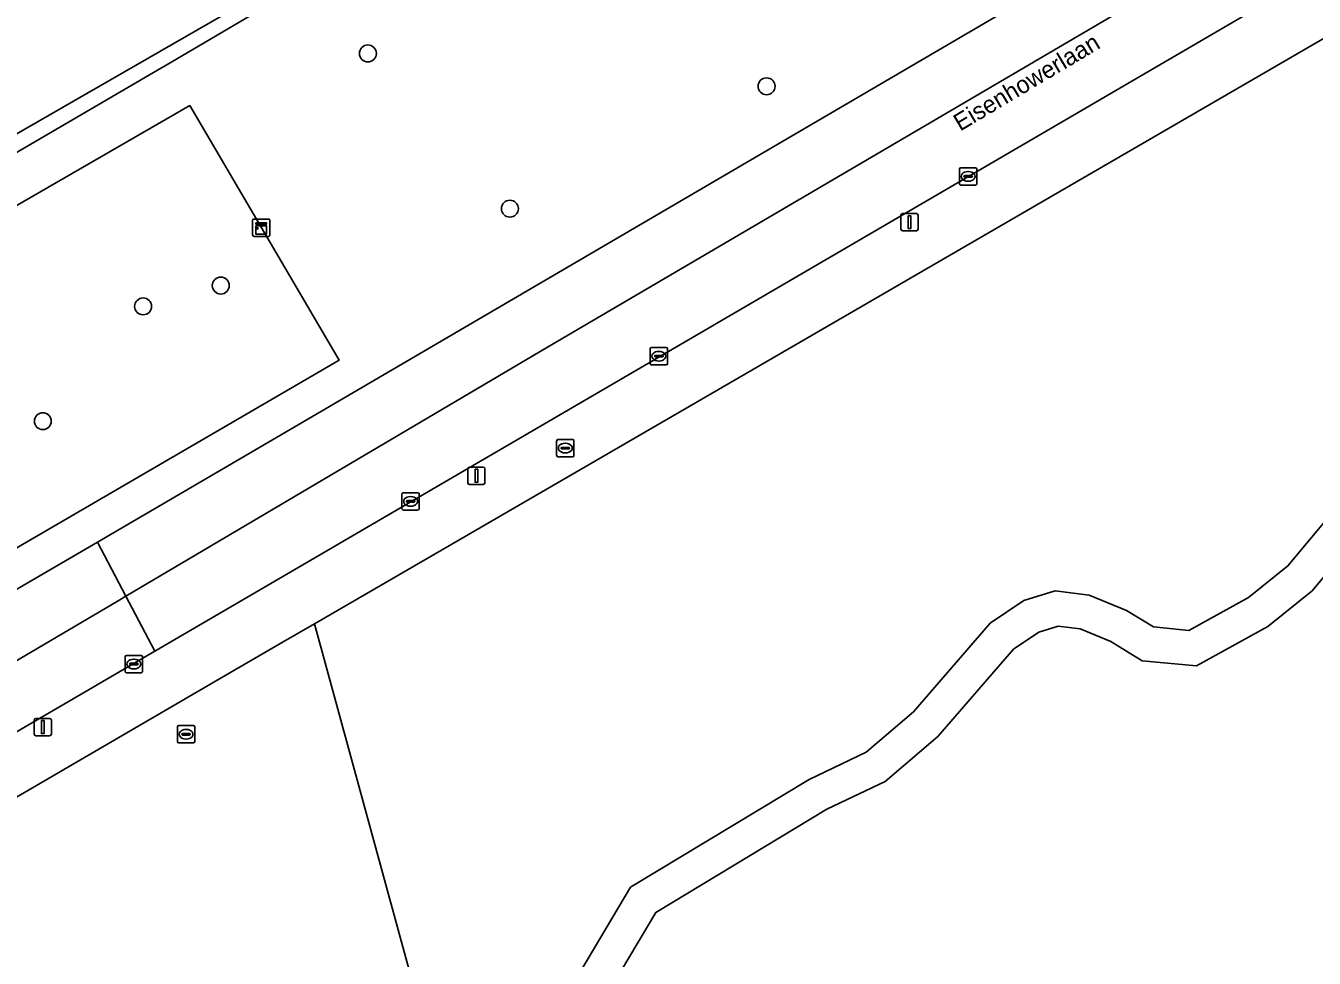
# Model space of a CAD drawing. Extents: x 162879 to 165540, y 384011 to 385181.
# Drawn here: x 163130.7 to 163205.2, y 384332.4 to 384386.3 of the extents above; entities that cross this region are included whole.
import ezdxf

# ---------------------------------------------------------------- set-up
doc = ezdxf.new("R2010")
doc.units = 0
for name, color, linetype in [('IMGEO_Berm_groen', 7, 'Continuous'), ('IMGEO_Boom', 7, 'Continuous'), ('IMGEO_Groenvoorziening', 7, 'Continuous'), ('IMGEO_Kast', 7, 'Continuous'), ('IMGEO_Kolk', 7, 'Continuous'), ('IMGEO_Lichtmast', 7, 'Continuous'), ('IMGEO_Loofbos', 7, 'Continuous'), ('IMGEO_Openbare_ruimte_label', 7, 'Continuous'), ('IMGEO_Rijbaan_regionaal_gesloten', 7, 'Continuous'), ('IMGEO_Rioolput', 7, 'Continuous'), ('IMGEO_Voetpad_onverhard', 7, 'Continuous')]:
    doc.layers.add(name, color=color, linetype=linetype)

msp = doc.modelspace()

# ---------------------------------------------------------------- linework, layer by layer
at = {"layer": 'IMGEO_Berm_groen'}
for points in [[(162958.296, 384257.287), (162992.107, 384275.576), (162992.774, 384275.937), (163000, 384279.879), (163047.71, 384305.906), (163065.69, 384316.128), (163134.875, 384356.468), (163142.16, 384360.715), (163149.867, 384365.229), (163197.962, 384393.395), (163222.445, 384407.821), (163353.264, 384484.905)], [(163290.991, 384473.343), (163273.206, 384463), (163256.317, 384453.078), (163211.461, 384426.757), (163138.843, 384384.023), (163138.358, 384383.738), (163124.723, 384375.774), (163103.614, 384363.445), (163068.795, 384343.295), (163033.81, 384323.482)]]:
    msp.add_lwpolyline(points, dxfattribs=at)
msp.add_lwpolyline([(163148.842, 384366.976), (163055.696, 384312.747), (162991.211, 384277.349), (162986.763, 384286.167), (162986.414, 384294.29), (162999.918, 384301.631), (163052.601, 384331.084), (163140.211, 384381.691)], close=True, dxfattribs=at)
at = {"layer": 'IMGEO_Boom'}
for centre in [(163150.504, 384384.702), (163173.541, 384382.804), (163158.709, 384375.733), (163142.004, 384371.289), (163137.518, 384370.087), (163131.724, 384363.452)]:
    msp.add_circle(centre, 0.489, dxfattribs=at)
at = {"layer": 'IMGEO_Groenvoorziening'}
for points in [[(163596.733, 384620.336), (163590.474, 384616.677), (163584.15, 384613.033), (163543.932, 384589.276), (163500, 384563.326), (163392.794, 384500), (163356.886, 384478.81), (163202.966, 384387.982), (163138.189, 384350.166), (163091.98, 384323.19), (163060.001, 384304.827), (163000, 384271.727), (162995.148, 384269.194), (162989.657, 384266.154), (162987.354, 384264.896)], [(162987.751, 384263.155), (162988.941, 384263.017), (163012.114, 384262.491), (163015.053, 384262.437), (163010.306, 384266.101), (163010.259, 384272.54), (163015.983, 384275.987), (163044.781, 384289.14), (163054.546, 384290.508), (163057.113, 384293.326), (163061.012, 384294.747), (163074.049, 384307.518), (163078.609, 384311.03), (163103.227, 384326.016), (163139.713, 384347.269), (163141.708, 384348.431), (163145.603, 384350.692), (163147.412, 384351.742), (163229.097, 384399.154), (163272.33, 384424.447), (163305.16, 384443.366)]]:
    msp.add_lwpolyline(points, dxfattribs=at)
at = {"layer": 'IMGEO_Kast'}
for p, q in [((163143.844, 384374.205), (163143.844, 384375.046)), ((163143.844, 384375.046), (163143.844, 384374.205)), ((163143.919, 384375.13), (163144.76, 384375.13)), ((163144.76, 384375.13), (163143.919, 384375.13)), ((163144.844, 384375.055), (163144.844, 384374.214)), ((163144.844, 384374.214), (163144.844, 384375.055)), ((163144.769, 384374.13), (163143.928, 384374.13)), ((163143.928, 384374.13), (163144.769, 384374.13))]:
    msp.add_line(p, q, dxfattribs=at)
for points in [[(163144.039, 384374.92), (163144.639, 384374.92), (163144.639, 384374.835), (163144.039, 384374.835), (163144.039, 384374.92)], [(163144.039, 384374.745), (163144.639, 384374.745), (163144.639, 384374.256), (163144.039, 384374.256), (163144.039, 384374.745)]]:
    msp.add_lwpolyline(points, dxfattribs=at)
msp.add_circle((163144.123, 384374.594), 0.0377, dxfattribs=at)
for centre, start, end in [((163143.922, 384375.052), 92.4484, 184.28452), ((163143.922, 384375.052), 92.4484, 184.28452), ((163144.766, 384375.052), 2.4484, 94.28452), ((163144.766, 384375.052), 2.4484, 94.28452), ((163143.922, 384374.208), 182.4484, 274.28452), ((163143.922, 384374.208), 182.4484, 274.28452), ((163144.766, 384374.208), 272.4484, 4.28452), ((163144.766, 384374.208), 272.4484, 4.28452)]:
    msp.add_arc(centre, 0.0779, start, end, dxfattribs=at)
at = {"layer": 'IMGEO_Kolk'}
for p, q in [((163184.684, 384377.173), (163184.684, 384378.025)), ((163184.759, 384378.099), (163185.611, 384378.099)), ((163185.172, 384377.879), (163185.197, 384377.879)), ((163185.685, 384378.025), (163185.685, 384377.173)), ((163184.943, 384377.593), (163184.943, 384377.605)), ((163185.381, 384377.556), (163184.983, 384377.556)), ((163184.986, 384377.642), (163185.384, 384377.642)), ((163185.195, 384377.319), (163185.17, 384377.319)), ((163185.427, 384377.605), (163185.427, 384377.593)), ((163185.611, 384377.099), (163184.759, 384377.099)), ((163166.817, 384366.782), (163166.817, 384367.634)), ((163166.892, 384367.708), (163167.744, 384367.708)), ((163167.305, 384367.488), (163167.33, 384367.488)), ((163167.818, 384367.634), (163167.818, 384366.782)), ((163167.744, 384366.708), (163166.892, 384366.708)), ((163167.076, 384367.202), (163167.076, 384367.214)), ((163167.514, 384367.165), (163167.116, 384367.165)), ((163167.119, 384367.251), (163167.517, 384367.251)), ((163167.328, 384366.928), (163167.303, 384366.928)), ((163167.56, 384367.214), (163167.56, 384367.202)), ((163152.548, 384359.319), (163153.4, 384359.319)), ((163152.473, 384358.393), (163152.473, 384359.245)), ((163152.732, 384358.813), (163152.732, 384358.825)), ((163153.17, 384358.776), (163152.772, 384358.776)), ((163152.775, 384358.862), (163153.173, 384358.862)), ((163152.984, 384358.539), (163152.959, 384358.539)), ((163152.961, 384359.099), (163152.986, 384359.099)), ((163153.216, 384358.825), (163153.216, 384358.813)), ((163153.474, 384359.245), (163153.474, 384358.393)), ((163153.4, 384358.319), (163152.548, 384358.319)), ((163136.485, 384348.992), (163136.485, 384349.844)), ((163136.56, 384349.918), (163137.412, 384349.918)), ((163136.973, 384349.698), (163136.998, 384349.698)), ((163137.486, 384349.844), (163137.486, 384348.992)), ((163137.412, 384348.918), (163136.56, 384348.918)), ((163136.744, 384349.412), (163136.744, 384349.424)), ((163137.182, 384349.375), (163136.784, 384349.375)), ((163136.787, 384349.461), (163137.185, 384349.461)), ((163136.996, 384349.138), (163136.971, 384349.138)), ((163137.228, 384349.424), (163137.228, 384349.412))]:
    msp.add_line(p, q, dxfattribs=at)
for points in [[(163184.684, 384377.173), (163184.684, 384378.025)], [(163184.759, 384378.099), (163185.611, 384378.099)], [(163185.685, 384378.025), (163185.685, 384377.173)], [(163185.611, 384377.099), (163184.759, 384377.099)], [(163166.817, 384366.782), (163166.817, 384367.634)], [(163166.892, 384367.708), (163167.744, 384367.708)], [(163167.818, 384367.634), (163167.818, 384366.782)], [(163167.744, 384366.708), (163166.892, 384366.708)], [(163152.548, 384359.319), (163153.4, 384359.319)], [(163152.473, 384358.393), (163152.473, 384359.245)], [(163153.474, 384359.245), (163153.474, 384358.393)], [(163153.4, 384358.319), (163152.548, 384358.319)], [(163136.485, 384348.992), (163136.485, 384349.844)], [(163136.56, 384349.918), (163137.412, 384349.918)], [(163137.486, 384349.844), (163137.486, 384348.992)], [(163137.412, 384348.918), (163136.56, 384348.918)]]:
    msp.add_lwpolyline(points, dxfattribs=at)
for centre, radius, start, end in [((163184.761, 384378.023), 0.0765, 91.55205, 178.44795), ((163184.761, 384378.023), 0.0765, 91.55205, 178.44795), ((163185.609, 384378.023), 0.0765, 1.55205, 88.44795), ((163185.609, 384378.023), 0.0765, 1.55205, 88.44795), ((163184.761, 384377.175), 0.0765, 181.55205, 268.44795), ((163184.761, 384377.175), 0.0765, 181.55205, 268.44795), ((163184.983, 384377.602), 0.0403, 85.87752, 175.75265), ((163184.98, 384377.592), 0.0366, 178.93798, 274.71019), ((163185.384, 384377.599), 0.043, 264.86636, 352.45326), ((163185.388, 384377.604), 0.0386, 1.73085, 96.63898), ((163185.609, 384377.175), 0.0765, 271.55205, 358.44795), ((163185.609, 384377.175), 0.0765, 271.55205, 358.44795), ((163166.894, 384367.632), 0.0765, 91.55205, 178.44795), ((163166.894, 384367.632), 0.0765, 91.55205, 178.44795), ((163167.742, 384367.632), 0.0765, 1.55205, 88.44795), ((163167.742, 384367.632), 0.0765, 1.55205, 88.44795), ((163166.894, 384366.784), 0.0765, 181.55205, 268.44795), ((163166.894, 384366.784), 0.0765, 181.55205, 268.44795), ((163167.116, 384367.211), 0.0403, 85.87752, 175.75265), ((163167.113, 384367.201), 0.0366, 178.93798, 274.71019), ((163167.517, 384367.208), 0.043, 264.86636, 352.45326), ((163167.521, 384367.213), 0.0386, 1.73085, 96.63898), ((163167.742, 384366.784), 0.0765, 271.55205, 358.44795), ((163167.742, 384366.784), 0.0765, 271.55205, 358.44795), ((163152.55, 384359.243), 0.0765, 91.55205, 178.44795), ((163152.55, 384359.243), 0.0765, 91.55205, 178.44795), ((163153.398, 384359.243), 0.0765, 1.55205, 88.44795), ((163153.398, 384359.243), 0.0765, 1.55205, 88.44795), ((163152.772, 384358.822), 0.0403, 85.87752, 175.75265), ((163152.769, 384358.812), 0.0366, 178.93798, 274.71019), ((163153.173, 384358.819), 0.043, 264.86636, 352.45326), ((163153.177, 384358.824), 0.0386, 1.73085, 96.63898), ((163152.55, 384358.395), 0.0765, 181.55205, 268.44795), ((163152.55, 384358.395), 0.0765, 181.55205, 268.44795), ((163153.398, 384358.395), 0.0765, 271.55205, 358.44795), ((163153.398, 384358.395), 0.0765, 271.55205, 358.44795), ((163136.562, 384349.842), 0.0765, 91.55205, 178.44795), ((163136.562, 384349.842), 0.0765, 91.55205, 178.44795), ((163137.41, 384349.842), 0.0765, 1.55205, 88.44795), ((163137.41, 384349.842), 0.0765, 1.55205, 88.44795), ((163136.562, 384348.994), 0.0765, 181.55205, 268.44795), ((163136.562, 384348.994), 0.0765, 181.55205, 268.44795), ((163136.784, 384349.421), 0.0403, 85.87752, 175.75265), ((163136.781, 384349.411), 0.0366, 178.93798, 274.71019), ((163137.185, 384349.418), 0.043, 264.86636, 352.45326), ((163137.189, 384349.423), 0.0386, 1.73085, 96.63898), ((163137.41, 384348.994), 0.0765, 271.55205, 358.44795), ((163137.41, 384348.994), 0.0765, 271.55205, 358.44795)]:
    msp.add_arc(centre, radius, start, end, dxfattribs=at)
for centre, major_axis, ratio, start_param, end_param in [((163185.171, 384377.599), (-0.387, 0.002), 0.722429, 4.712389, 7.853982), ((163185.196, 384377.599), (-0.39, 0.002), 0.717154, 1.570796, 4.712389), ((163167.304, 384367.208), (-0.387, 0.002), 0.722429, 4.712389, 7.853982), ((163167.329, 384367.208), (-0.39, 0.002), 0.717154, 1.570796, 4.712389), ((163152.96, 384358.819), (-0.387, 0.002), 0.722429, 4.712389, 7.853982), ((163152.985, 384358.819), (-0.39, 0.002), 0.717154, 1.570796, 4.712389), ((163136.972, 384349.418), (-0.387, 0.002), 0.722429, 4.712389, 7.853982), ((163136.997, 384349.418), (-0.39, 0.002), 0.717154, 1.570796, 4.712389)]:
    msp.add_ellipse(centre, major_axis=major_axis, ratio=ratio, start_param=start_param, end_param=end_param, dxfattribs=at)
at = {"layer": 'IMGEO_Lichtmast'}
for p, q in [((163181.302, 384374.553), (163181.302, 384375.353)), ((163181.302, 384375.353), (163181.302, 384374.553)), ((163181.402, 384375.453), (163182.192, 384375.453)), ((163182.192, 384375.453), (163181.402, 384375.453)), ((163182.292, 384375.353), (163182.292, 384374.553)), ((163182.292, 384374.553), (163182.292, 384375.353)), ((163182.192, 384374.453), (163181.402, 384374.453)), ((163181.402, 384374.453), (163182.192, 384374.453)), ((163156.378, 384360.799), (163157.168, 384360.799)), ((163157.168, 384360.799), (163156.378, 384360.799)), ((163156.278, 384359.899), (163156.278, 384360.699)), ((163156.278, 384360.699), (163156.278, 384359.899)), ((163157.268, 384360.699), (163157.268, 384359.899)), ((163157.268, 384359.899), (163157.268, 384360.699)), ((163157.168, 384359.799), (163156.378, 384359.799)), ((163156.378, 384359.799), (163157.168, 384359.799)), ((163131.227, 384345.372), (163131.227, 384346.172)), ((163131.227, 384346.172), (163131.227, 384345.372)), ((163131.327, 384346.272), (163132.117, 384346.272)), ((163132.117, 384346.272), (163131.327, 384346.272)), ((163132.217, 384346.172), (163132.217, 384345.372)), ((163132.217, 384345.372), (163132.217, 384346.172)), ((163132.117, 384345.272), (163131.327, 384345.272)), ((163131.327, 384345.272), (163132.117, 384345.272))]:
    msp.add_line(p, q, dxfattribs=at)
for points in [[(163181.722, 384375.328), (163181.872, 384375.328), (163181.872, 384374.578), (163181.722, 384374.578), (163181.722, 384375.328)], [(163156.698, 384360.674), (163156.848, 384360.674), (163156.848, 384359.924), (163156.698, 384359.924), (163156.698, 384360.674)], [(163131.647, 384346.147), (163131.797, 384346.147), (163131.797, 384345.397), (163131.647, 384345.397), (163131.647, 384346.147)]]:
    msp.add_lwpolyline(points, dxfattribs=at)
for centre, start, end in [((163181.402, 384375.353), 90, 180), ((163181.402, 384375.353), 90, 180), ((163182.192, 384375.353), 0, 90), ((163182.192, 384375.353), 360, 90), ((163181.402, 384374.553), 180, 270), ((163181.402, 384374.553), 180, 270), ((163182.192, 384374.553), 270, 0), ((163182.192, 384374.553), 270, 0), ((163156.378, 384360.699), 90, 180), ((163156.378, 384360.699), 90, 180), ((163157.168, 384360.699), 0, 90), ((163157.168, 384360.699), 360, 90), ((163156.378, 384359.899), 180, 270), ((163156.378, 384359.899), 180, 270), ((163157.168, 384359.899), 270, 0), ((163157.168, 384359.899), 270, 0), ((163131.327, 384346.172), 90, 180), ((163131.327, 384346.172), 90, 180), ((163132.117, 384346.172), 0, 90), ((163132.117, 384346.172), 360, 90), ((163131.327, 384345.372), 180, 270), ((163131.327, 384345.372), 180, 270), ((163132.117, 384345.372), 270, 0), ((163132.117, 384345.372), 270, 0)]:
    msp.add_arc(centre, 0.1, start, end, dxfattribs=at)
at = {"layer": 'IMGEO_Loofbos'}
for points in [[(163229.097, 384399.154), (163147.412, 384351.742), (163158.27, 384312.081), (163162.156, 384313.029), (163160.013, 384319.249), (163159.169, 384324.318), (163160.73, 384328.191), (163165.672, 384336.523), (163175.991, 384342.737), (163179.291, 384344.325), (163182.035, 384346.651), (163186.463, 384351.781), (163188.392, 384353.092), (163190.215, 384353.652), (163192.179, 384353.396), (163194.341, 384352.514), (163195.894, 384351.559), (163197.94, 384351.366), (163201.376, 384353.257), (163203.656, 384355.092), (163207.856, 384360.119)], [(163209.662, 384359.161), (163205.064, 384353.658), (163202.49, 384351.586), (163198.379, 384349.316), (163195.243, 384349.611), (163193.434, 384350.724), (163191.664, 384351.446), (163190.387, 384351.613), (163189.268, 384351.268), (163187.81, 384350.278), (163183.442, 384345.222), (163180.387, 384342.633), (163177.023, 384341.024), (163167.135, 384335.069), (163162.528, 384327.302), (163161.234, 384324.092), (163161.959, 384319.742), (163164.107, 384313.505), (163168.868, 384314.666), (163182.164, 384318.052), (163184.827, 384316.897)], [(163130.038, 384303.169), (163140.765, 384307.422), (163143.627, 384308.496), (163152.808, 384310.825), (163155.41, 384311.383), (163158.27, 384312.081), (163147.412, 384351.742), (163145.603, 384350.692), (163141.708, 384348.431), (163139.713, 384347.269), (163103.227, 384326.016)]]:
    msp.add_lwpolyline(points, dxfattribs=at)
msp.add_lwpolyline([(163140.211, 384381.691), (163052.601, 384331.084), (162999.918, 384301.631), (162986.414, 384294.29), (162986.763, 384286.167), (162991.211, 384277.349), (163055.696, 384312.747), (163148.842, 384366.976)], close=True, dxfattribs=at)
at = {"layer": 'IMGEO_Rijbaan_regionaal_gesloten'}
for points in [[(163488.662, 384588.942), (163262.486, 384457.037), (163154.214, 384393.894), (163124.264, 384376.647), (163124.723, 384375.774), (163138.358, 384383.738), (163138.843, 384384.023), (163211.461, 384426.757), (163256.317, 384453.078), (163273.206, 384463), (163290.991, 384473.343)], [(163075.431, 384317.808), (163102.908, 384333.537), (163136.085, 384353.074), (163136.524, 384353.333), (163134.875, 384356.468), (163065.69, 384316.128), (163047.71, 384305.906), (163000, 384279.879), (162992.774, 384275.937), (162992.107, 384275.576), (162958.296, 384257.287)], [(163060.001, 384304.827), (163091.98, 384323.19), (163138.189, 384350.166), (163136.524, 384353.333), (163136.085, 384353.074), (163102.908, 384333.537), (163075.431, 384317.808), (163019.119, 384286.121), (162984.518, 384267.432), (162966.682, 384257.842), (162956.166, 384251.683), (162950.166, 384247.581), (162946.914, 384245.082), (162943.802, 384242.49), (162940.823, 384239.608), (162938.038, 384236.628), (162940.725, 384234.294)]]:
    msp.add_lwpolyline(points, dxfattribs=at)
for points in [[(163354.963, 384482.045), (163353.264, 384484.905), (163222.445, 384407.821), (163197.962, 384393.395), (163149.867, 384365.229), (163142.16, 384360.715), (163134.875, 384356.468), (163136.524, 384353.333), (163160.883, 384367.724), (163225.608, 384405.722), (163256.03, 384423.663), (163336.414, 384471.12), (163346.799, 384477.262)], [(163356.886, 384478.81), (163354.963, 384482.045), (163346.799, 384477.262), (163336.414, 384471.12), (163256.03, 384423.663), (163225.608, 384405.722), (163160.883, 384367.724), (163136.524, 384353.333), (163138.189, 384350.166), (163202.966, 384387.982)]]:
    msp.add_lwpolyline(points, close=True, dxfattribs=at)
at = {"layer": 'IMGEO_Rioolput'}
for p, q in [((163161.411, 384361.47), (163161.411, 384362.322)), ((163161.486, 384362.396), (163162.338, 384362.396)), ((163162.412, 384362.322), (163162.412, 384361.47)), ((163161.67, 384361.89), (163161.67, 384361.902)), ((163162.108, 384361.853), (163161.71, 384361.853)), ((163161.713, 384361.939), (163162.111, 384361.939)), ((163161.922, 384361.616), (163161.897, 384361.616)), ((163161.899, 384362.176), (163161.924, 384362.176)), ((163162.154, 384361.902), (163162.154, 384361.89)), ((163162.338, 384361.396), (163161.486, 384361.396)), ((163139.574, 384345.86), (163140.426, 384345.86)), ((163139.499, 384344.934), (163139.499, 384345.786)), ((163139.758, 384345.354), (163139.758, 384345.366)), ((163140.196, 384345.317), (163139.798, 384345.317)), ((163139.801, 384345.403), (163140.199, 384345.403)), ((163139.987, 384345.64), (163140.012, 384345.64)), ((163140.242, 384345.366), (163140.242, 384345.354)), ((163140.5, 384345.786), (163140.5, 384344.934)), ((163140.426, 384344.86), (163139.574, 384344.86)), ((163140.01, 384345.08), (163139.985, 384345.08))]:
    msp.add_line(p, q, dxfattribs=at)
for points in [[(163161.411, 384361.47), (163161.411, 384362.322)], [(163161.486, 384362.396), (163162.338, 384362.396)], [(163162.412, 384362.322), (163162.412, 384361.47)], [(163162.338, 384361.396), (163161.486, 384361.396)], [(163139.574, 384345.86), (163140.426, 384345.86)], [(163139.499, 384344.934), (163139.499, 384345.786)], [(163140.5, 384345.786), (163140.5, 384344.934)], [(163140.426, 384344.86), (163139.574, 384344.86)]]:
    msp.add_lwpolyline(points, dxfattribs=at)
for centre, radius, start, end in [((163161.488, 384362.32), 0.0765, 91.55205, 178.44795), ((163161.488, 384362.32), 0.0765, 91.55205, 178.44795), ((163162.336, 384362.32), 0.0765, 1.55205, 88.44795), ((163162.336, 384362.32), 0.0765, 1.55205, 88.44795), ((163161.71, 384361.899), 0.0403, 85.87752, 175.75265), ((163161.707, 384361.889), 0.0366, 178.93798, 274.71019), ((163162.111, 384361.896), 0.043, 264.86636, 352.45326), ((163162.115, 384361.901), 0.0386, 1.73085, 96.63898), ((163161.488, 384361.472), 0.0765, 181.55205, 268.44795), ((163161.488, 384361.472), 0.0765, 181.55205, 268.44795), ((163162.336, 384361.472), 0.0765, 271.55205, 358.44795), ((163162.336, 384361.472), 0.0765, 271.55205, 358.44795), ((163139.576, 384345.784), 0.0765, 91.55205, 178.44795), ((163139.576, 384345.784), 0.0765, 91.55205, 178.44795), ((163140.424, 384345.784), 0.0765, 1.55205, 88.44795), ((163140.424, 384345.784), 0.0765, 1.55205, 88.44795), ((163139.798, 384345.363), 0.0403, 85.87752, 175.75265), ((163139.795, 384345.353), 0.0366, 178.93798, 274.71019), ((163140.199, 384345.36), 0.043, 264.86636, 352.45326), ((163140.203, 384345.365), 0.0386, 1.73085, 96.63898), ((163139.576, 384344.936), 0.0765, 181.55205, 268.44795), ((163139.576, 384344.936), 0.0765, 181.55205, 268.44795), ((163140.424, 384344.936), 0.0765, 271.55205, 358.44795), ((163140.424, 384344.936), 0.0765, 271.55205, 358.44795)]:
    msp.add_arc(centre, radius, start, end, dxfattribs=at)
for centre, major_axis, ratio, start_param, end_param in [((163161.898, 384361.896), (-0.387, 0.002), 0.722429, 4.712389, 7.853982), ((163161.923, 384361.896), (-0.39, 0.002), 0.717154, 1.570796, 4.712389), ((163139.986, 384345.36), (-0.387, 0.002), 0.722429, 4.712389, 7.853982), ((163140.011, 384345.36), (-0.39, 0.002), 0.717154, 1.570796, 4.712389)]:
    msp.add_ellipse(centre, major_axis=major_axis, ratio=ratio, start_param=start_param, end_param=end_param, dxfattribs=at)
at = {"layer": 'IMGEO_Voetpad_onverhard'}
for points in [[(163207.856, 384360.119), (163203.656, 384355.092), (163201.376, 384353.257), (163197.94, 384351.366), (163195.894, 384351.559), (163194.341, 384352.514), (163192.179, 384353.396), (163190.215, 384353.652), (163188.392, 384353.092), (163186.463, 384351.781), (163182.035, 384346.651), (163179.291, 384344.325), (163175.991, 384342.737), (163165.672, 384336.523), (163160.73, 384328.191)], [(163162.528, 384327.302), (163167.135, 384335.069), (163177.023, 384341.024), (163180.387, 384342.633), (163183.442, 384345.222), (163187.81, 384350.278), (163189.268, 384351.268), (163190.387, 384351.613), (163191.664, 384351.446), (163193.434, 384350.724), (163195.243, 384349.611), (163198.379, 384349.316), (163202.49, 384351.586), (163205.064, 384353.658), (163209.662, 384359.161)]]:
    msp.add_lwpolyline(points, dxfattribs=at)

# ---------------------------------------------------------------- texts
at = {"layer": 'IMGEO_Openbare_ruimte_label'}
msp.add_text('Eisenhowerlaan', height=1, rotation=30.79671, dxfattribs=at).set_placement((163184.723, 384380.182))

doc.saveas('drawing.dxf')
